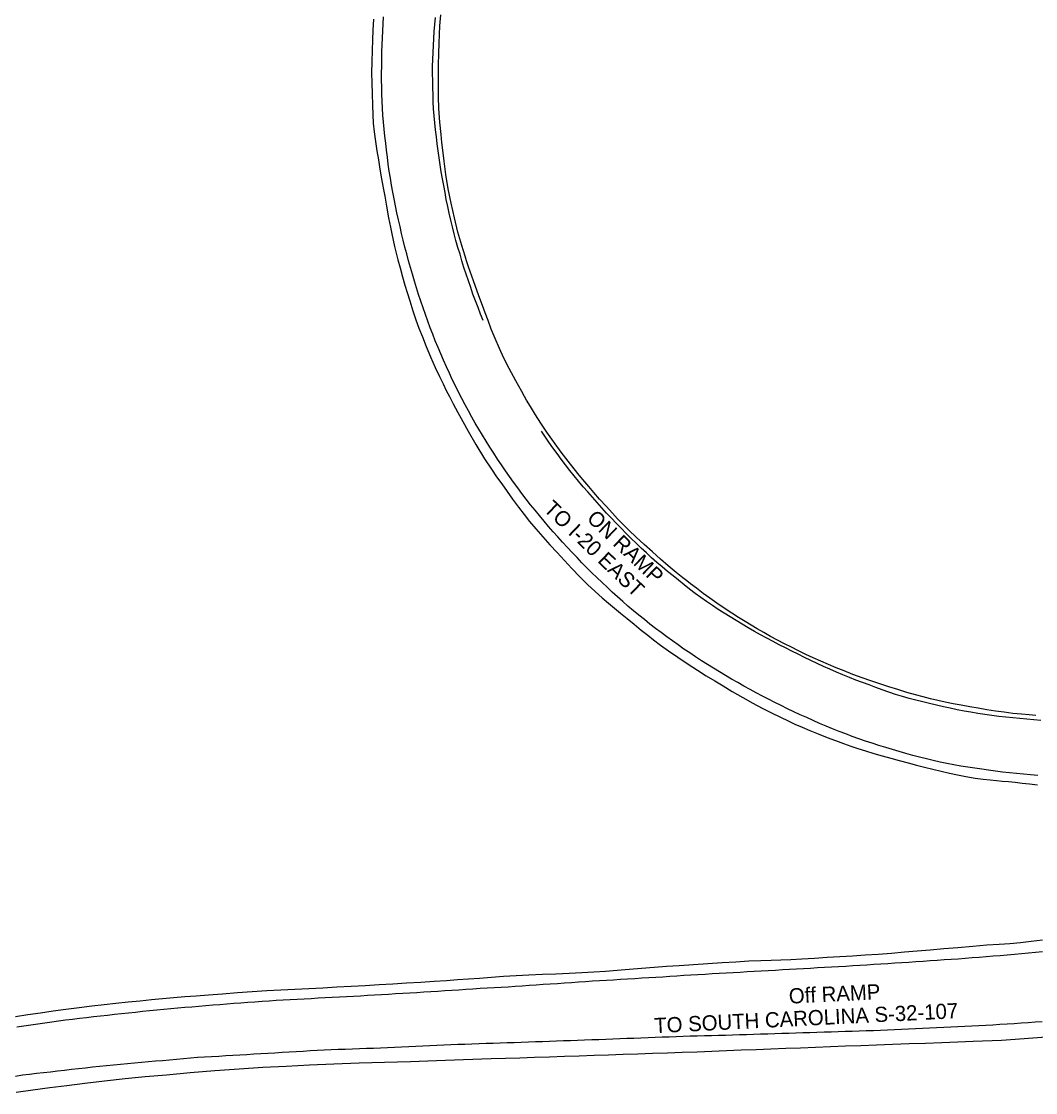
# Model space of a CAD drawing. Extents: x 1961683 to 1977751, y 798292 to 805767.
# Drawn here: x 1963000.6 to 1963360.5, y 799190.8 to 799570.9 of the extents above; entities that cross this region are included whole.
import ezdxf

# ---------------------------------------------------------------- set-up
doc = ezdxf.new("R2010")
doc.units = 0
for name, color, linetype in [('RD_EX_Road', 7, 'Continuous'), ('RD_EX_Road_Paint', 7, 'Continuous'), ('RD_TX_RoadID', 7, 'Continuous')]:
    doc.layers.add(name, color=color, linetype=linetype)

msp = doc.modelspace()

# ---------------------------------------------------------------- linework, layer by layer
at = {"layer": 'RD_EX_Road'}
for points in [[(1963125.57, 799571.68), (1963125.33, 799567.81), (1963125.16, 799564.4), (1963125.02, 799560.65), (1963124.91, 799556.54), (1963124.9, 799552.68), (1963124.97, 799549.1), (1963125.05, 799545.27), (1963125.15, 799541.23), (1963125.27, 799537.74), (1963125.45, 799534.81), (1963125.77, 799531.7), (1963126.23, 799528.35), (1963126.74, 799525.06), (1963127.28, 799521.83), (1963127.85, 799518.49), (1963128.44, 799515.05), (1963129, 799511.89), (1963129.54, 799508.92), (1963130.19, 799505.36), (1963130.92, 799501.27), (1963131.53, 799497.95), (1963132, 799495.5), (1963132.48, 799493.24), (1963132.99, 799491.02), (1963133.56, 799488.74), (1963134.19, 799486.34), (1963134.98, 799483.5), (1963135.89, 799480.28), (1963136.71, 799477.37), (1963137.47, 799474.77), (1963138.39, 799471.74), (1963139.5, 799468.25), (1963140.59, 799465.02), (1963141.67, 799462.08), (1963142.88, 799458.95), (1963144.26, 799455.56), (1963145.8, 799451.91), (1963147.46, 799448.13), (1963148.95, 799444.9), (1963150.23, 799442.28), (1963151.37, 799439.99), (1963152.46, 799437.87), (1963153.84, 799435.25), (1963155.52, 799432.09), (1963157.25, 799428.89), (1963159.09, 799425.53), (1963161.81, 799420.83), (1963164.97, 799415.67), (1963167.37, 799412.03), (1963169.22, 799409.36), (1963171.05, 799406.79), (1963172.94, 799404.15), (1963174.92, 799401.4), (1963176.99, 799398.57), (1963178.97, 799395.95), (1963180.9, 799393.51), (1963183.11, 799390.87), (1963185.6, 799387.99), (1963188.14, 799385.17), (1963190.67, 799382.43), (1963193.28, 799379.61), (1963195.97, 799376.72), (1963198.74, 799373.85), (1963201.54, 799371.06), (1963204.21, 799368.56), (1963206.7, 799366.38), (1963208.96, 799364.44), (1963211.04, 799362.69), (1963213.23, 799360.89), (1963215.57, 799358.98), (1963218.03, 799356.97), (1963220.56, 799354.91), (1963222.84, 799353.08), (1963224.9, 799351.45), (1963227.34, 799349.62), (1963230.24, 799347.54), (1963233.54, 799345.27), (1963237.16, 799342.88), (1963240.55, 799340.69), (1963243.64, 799338.74), (1963246.61, 799336.89), (1963249.56, 799335.09), (1963252.87, 799333.11), (1963256.55, 799330.98), (1963260.1, 799329.02), (1963263.48, 799327.25), (1963266.76, 799325.59), (1963269.93, 799324.03), (1963272.69, 799322.69), (1963275.09, 799321.56), (1963277.63, 799320.42), (1963280.41, 799319.26), (1963283.37, 799318.05), (1963286.49, 799316.83), (1963289.47, 799315.7), (1963292.27, 799314.68), (1963294.88, 799313.76), (1963297.36, 799312.91), (1963300.1, 799312.02), (1963303.1, 799311.11), (1963306.09, 799310.26), (1963309.06, 799309.47), (1963312.12, 799308.64), (1963315.25, 799307.77), (1963318.24, 799306.96), (1963321.07, 799306.22), (1963323.98, 799305.5), (1963326.97, 799304.79), (1963329.87, 799304.13), (1963332.71, 799303.52), (1963335.77, 799302.94), (1963339.01, 799302.42), (1963341.91, 799302.04), (1963344.38, 799301.78), (1963346.61, 799301.56), (1963348.66, 799301.35), (1963350.84, 799301.14), (1963353.19, 799300.9), (1963355.68, 799300.62), (1963358.31, 799300.31), (1963361.12, 799300.01)], [(1963360.54, 799324.62), (1963358.18, 799324.8), (1963355.44, 799325.03), (1963352.45, 799325.33), (1963349.34, 799325.73), (1963346.21, 799326.19), (1963343.16, 799326.67), (1963340.15, 799327.16), (1963337.11, 799327.68), (1963334.12, 799328.22), (1963331.21, 799328.76), (1963328.42, 799329.32), (1963325.77, 799329.91), (1963323.18, 799330.52), (1963320.59, 799331.17), (1963317.86, 799331.92), (1963314.84, 799332.81), (1963311.65, 799333.78), (1963308.44, 799334.78), (1963305.23, 799335.81), (1963302.07, 799336.86), (1963298.9, 799337.97), (1963295.68, 799339.18), (1963292.58, 799340.4), (1963289.74, 799341.56), (1963287.03, 799342.7), (1963284.31, 799343.86), (1963281.6, 799345.06), (1963278.93, 799346.3), (1963276.33, 799347.56), (1963273.86, 799348.82), (1963271.41, 799350.09), (1963268.9, 799351.38), (1963266.4, 799352.7), (1963264.01, 799354.06), (1963261.73, 799355.41), (1963259.56, 799356.69), (1963257.39, 799357.99), (1963255.11, 799359.41), (1963252.66, 799360.97), (1963250.01, 799362.71), (1963247.36, 799364.5), (1963244.91, 799366.22), (1963242.54, 799367.94), (1963240.13, 799369.74), (1963238.05, 799371.3), (1963236.71, 799372.34), (1963235.28, 799373.48), (1963232.95, 799375.37), (1963230.16, 799377.69), (1963227.36, 799380.1), (1963224.51, 799382.64), (1963221.57, 799385.31), (1963218.73, 799387.94), (1963216.18, 799390.37), (1963213.97, 799392.55), (1963212.14, 799394.42), (1963210.3, 799396.39), (1963208.06, 799398.84), (1963205.76, 799401.43), (1963203.72, 799403.77), (1963201.96, 799405.83), (1963200.49, 799407.57), (1963198.57, 799409.9), (1963195.5, 799413.76), (1963192.15, 799418.09), (1963189.39, 799421.82), (1963187.04, 799425.15), (1963184.92, 799428.31), (1963182.99, 799431.32), (1963181.23, 799434.22), (1963179.87, 799436.54), (1963179.14, 799437.83), (1963178.17, 799439.59), (1963176.09, 799443.32), (1963173.7, 799447.71), (1963171.81, 799451.44), (1963170.21, 799454.89), (1963168.69, 799458.39), (1963167.32, 799461.75), (1963166.18, 799464.75), (1963165.17, 799467.5), (1963164.19, 799470.1), (1963162.91, 799473.57), (1963160.99, 799478.91), (1963159.25, 799483.81), (1963158.53, 799485.92), (1963158.02, 799487.63), (1963156.89, 799491.35), (1963155.51, 799496.19), (1963154.24, 799501.24), (1963153.09, 799506.4), (1963152.09, 799511.57), (1963151.25, 799516.59), (1963150.59, 799521.33), (1963150.11, 799525.28), (1963149.82, 799527.95), (1963149.54, 799530.78), (1963149.14, 799535.21), (1963148.78, 799540.07), (1963148.63, 799544.17), (1963148.6, 799547.92), (1963148.6, 799551.71), (1963148.62, 799555.56), (1963148.7, 799559.52), (1963148.8, 799563.22), (1963148.93, 799566.29), (1963149.12, 799569.41), (1963149.43, 799573.25)], [(1963362.91, 799244.86), (1963358.9, 799244.42), (1963355.11, 799243.98), (1963351.37, 799243.61), (1963347.49, 799243.34), (1963343.18, 799243.06), (1963338.17, 799242.65), (1963332.92, 799242.19), (1963327.89, 799241.74), (1963323.07, 799241.32), (1963318.51, 799240.93), (1963314, 799240.56), (1963309.36, 799240.17), (1963304.67, 799239.8), (1963300.02, 799239.49), (1963295.46, 799239.21), (1963291.02, 799238.94), (1963286.57, 799238.68), (1963281.99, 799238.41), (1963277.57, 799238.14), (1963273.63, 799237.91), (1963270.03, 799237.74), (1963266.64, 799237.65), (1963263.02, 799237.56), (1963258.74, 799237.37), (1963254.06, 799237.11), (1963249.23, 799236.82), (1963244.23, 799236.5), (1963239.07, 799236.16), (1963234.04, 799235.82), (1963229.48, 799235.5), (1963225.11, 799235.16), (1963220.68, 799234.78), (1963216.29, 799234.41), (1963212.04, 799234.07), (1963207.88, 799233.78), (1963203.73, 799233.52), (1963199.46, 799233.27), (1963194.96, 799233.05), (1963190.27, 799232.84), (1963185.46, 799232.64), (1963180.7, 799232.44), (1963176.14, 799232.22), (1963171.72, 799231.95), (1963167.36, 799231.63), (1963163.16, 799231.3), (1963159.24, 799231.02), (1963155.39, 799230.74), (1963151.4, 799230.45), (1963147.1, 799230.15), (1963142.29, 799229.85), (1963137.31, 799229.56), (1963132.46, 799229.26), (1963127.61, 799228.98), (1963122.65, 799228.71), (1963117.63, 799228.44), (1963112.59, 799228.15), (1963107.56, 799227.86), (1963102.57, 799227.59), (1963097.62, 799227.33), (1963092.7, 799227.11), (1963087.72, 799226.86), (1963082.55, 799226.53), (1963077.28, 799226.14), (1963072.03, 799225.73), (1963067.06, 799225.34), (1963062.65, 799225.02), (1963058.57, 799224.72), (1963054.6, 799224.38), (1963050.7, 799224.03), (1963046.8, 799223.67), (1963042.78, 799223.28), (1963038.48, 799222.84), (1963034.13, 799222.38), (1963029.93, 799221.93), (1963025.65, 799221.45), (1963021.06, 799220.88), (1963016.39, 799220.25), (1963011.87, 799219.63), (1963007.41, 799219), (1963002.96, 799218.35), (1962998.51, 799217.68)], [(1963364.27, 799210.46), (1963356.46, 799209.83), (1963348.36, 799209.32), (1963338.38, 799208.87), (1963332.86, 799208.66), (1963327.22, 799208.45), (1963321.46, 799208.24), (1963315.57, 799208.04), (1963309.69, 799207.84), (1963303.97, 799207.63), (1963298.41, 799207.42), (1963293, 799207.2), (1963287.68, 799206.99), (1963282.38, 799206.78), (1963277.09, 799206.58), (1963271.81, 799206.38), (1963266.55, 799206.18), (1963261.3, 799205.98), (1963256.06, 799205.78), (1963250.82, 799205.58), (1963245.58, 799205.38), (1963240.34, 799205.18), (1963235.09, 799204.99), (1963229.83, 799204.81), (1963224.58, 799204.62), (1963219.36, 799204.44), (1963214.16, 799204.26), (1963208.98, 799204.08), (1963203.79, 799203.9), (1963198.57, 799203.73), (1963193.3, 799203.55), (1963188, 799203.38), (1963182.72, 799203.21), (1963177.52, 799203.04), (1963172.39, 799202.87), (1963167.34, 799202.71), (1963157.49, 799202.37), (1963147.94, 799202.01), (1963138.63, 799201.68), (1963129.45, 799201.42), (1963120.41, 799201.17), (1963111.53, 799200.86), (1963102.88, 799200.5), (1963094.51, 799200.09), (1963086.23, 799199.64), (1963077.86, 799199.11), (1963069.31, 799198.5), (1963060.52, 799197.76), (1963052.06, 799197), (1963044.54, 799196.31), (1963037.41, 799195.61), (1963030.14, 799194.81), (1963023.12, 799193.99), (1963016.76, 799193.23), (1963010.73, 799192.47), (1963004.69, 799191.64), (1962998.77, 799190.78)]]:
    msp.add_lwpolyline(points, dxfattribs=at)
at = {"layer": 'RD_EX_Road_Paint'}
for points in [[(1963361.21, 799303.35), (1963358.72, 799303.53), (1963356.23, 799303.75), (1963353.74, 799303.98), (1963351.25, 799304.23), (1963348.77, 799304.51), (1963346.3, 799304.83), (1963343.82, 799305.17), (1963341.35, 799305.53), (1963338.88, 799305.88), (1963336.4, 799306.24), (1963333.94, 799306.64), (1963331.48, 799307.08), (1963329.03, 799307.57), (1963326.59, 799308.08), (1963324.15, 799308.64), (1963321.72, 799309.22), (1963319.3, 799309.83), (1963316.88, 799310.45), (1963314.47, 799311.11), (1963312.07, 799311.81), (1963309.67, 799312.52), (1963307.28, 799313.24), (1963304.9, 799313.98), (1963302.51, 799314.73), (1963300.14, 799315.52), (1963297.78, 799316.34), (1963295.44, 799317.2), (1963293.1, 799318.07), (1963290.77, 799318.98), (1963288.45, 799319.91), (1963286.14, 799320.86), (1963283.83, 799321.82), (1963281.54, 799322.82), (1963279.26, 799323.84), (1963276.99, 799324.88), (1963274.72, 799325.93), (1963272.47, 799327), (1963270.22, 799328.1), (1963267.99, 799329.22), (1963265.76, 799330.36), (1963263.55, 799331.51), (1963261.34, 799332.68), (1963259.14, 799333.87), (1963256.95, 799335.07), (1963254.77, 799336.29), (1963252.59, 799337.52), (1963250.44, 799338.79), (1963248.3, 799340.08), (1963246.17, 799341.39), (1963244.04, 799342.7), (1963241.93, 799344.04), (1963239.84, 799345.41), (1963237.76, 799346.8), (1963235.7, 799348.2), (1963233.65, 799349.63), (1963231.6, 799351.07), (1963229.58, 799352.54), (1963227.57, 799354.02), (1963225.58, 799355.53), (1963223.61, 799357.07), (1963221.65, 799358.62), (1963219.7, 799360.18), (1963217.76, 799361.77), (1963215.84, 799363.37), (1963213.96, 799365.01), (1963212.12, 799366.7), (1963210.28, 799368.4), (1963208.46, 799370.11), (1963206.64, 799371.82), (1963204.82, 799373.53), (1963203.02, 799375.27), (1963201.25, 799377.04), (1963199.5, 799378.82), (1963197.77, 799380.62), (1963196.05, 799382.43), (1963194.33, 799384.25), (1963192.64, 799386.09), (1963190.97, 799387.96), (1963189.32, 799389.83), (1963187.67, 799391.71), (1963186.05, 799393.61), (1963184.44, 799395.53), (1963182.86, 799397.46), (1963181.29, 799399.41), (1963179.75, 799401.38), (1963178.23, 799403.36), (1963176.73, 799405.36), (1963175.26, 799407.38), (1963173.81, 799409.42), (1963172.38, 799411.47), (1963170.97, 799413.53), (1963169.57, 799415.6), (1963168.2, 799417.7), (1963166.86, 799419.81), (1963165.53, 799421.93), (1963164.21, 799424.05), (1963162.92, 799426.19), (1963161.66, 799428.35), (1963160.43, 799430.52), (1963159.23, 799432.71), (1963158.04, 799434.91), (1963156.87, 799437.12), (1963155.72, 799439.34), (1963154.6, 799441.58), (1963153.51, 799443.83), (1963152.46, 799446.1), (1963151.43, 799448.38), (1963150.42, 799450.66), (1963149.42, 799452.95), (1963148.44, 799455.25), (1963147.49, 799457.56), (1963146.57, 799459.89), (1963145.68, 799462.22), (1963144.8, 799464.56), (1963143.96, 799466.92), (1963143.15, 799469.28), (1963142.34, 799471.65), (1963141.55, 799474.02), (1963140.78, 799476.4), (1963140.06, 799478.79), (1963139.34, 799481.19), (1963138.62, 799483.58), (1963137.94, 799485.99), (1963137.32, 799488.41), (1963136.69, 799490.83), (1963136.06, 799493.25), (1963135.47, 799495.68), (1963134.96, 799498.12), (1963134.44, 799500.57), (1963133.88, 799503.01), (1963133.37, 799505.45), (1963132.91, 799507.91), (1963132.45, 799510.37), (1963131.98, 799512.82), (1963131.54, 799515.28), (1963131.16, 799517.75), (1963130.8, 799520.23), (1963130.5, 799522.71), (1963130.2, 799525.19), (1963129.88, 799527.67), (1963129.59, 799530.15), (1963129.34, 799532.64), (1963129.11, 799535.13), (1963128.91, 799537.62), (1963128.74, 799540.11), (1963128.62, 799542.61), (1963128.52, 799545.11), (1963128.47, 799547.61), (1963128.44, 799550.11), (1963128.44, 799552.6), (1963128.46, 799555.1), (1963128.5, 799557.6), (1963128.55, 799560.1), (1963128.62, 799562.6), (1963128.71, 799565.1), (1963128.82, 799567.6), (1963128.96, 799570.09), (1963129.12, 799572.59)], [(1963164.48, 799464.76), (1963163.56, 799467.09), (1963162.64, 799469.41), (1963161.75, 799471.75), (1963160.85, 799474.08), (1963160.08, 799476.46), (1963159.31, 799478.84), (1963158.48, 799481.19), (1963157.65, 799483.55), (1963156.95, 799485.95), (1963156.25, 799488.35), (1963155.52, 799490.74), (1963154.79, 799493.13), (1963154.19, 799495.56), (1963153.58, 799497.98), (1963153.01, 799500.42), (1963152.45, 799502.86), (1963151.91, 799505.3), (1963151.37, 799507.74), (1963150.94, 799510.2), (1963150.52, 799512.66), (1963150.06, 799515.12), (1963149.59, 799517.58), (1963149.21, 799520.05), (1963148.84, 799522.52), (1963148.49, 799524.99), (1963148.15, 799527.47), (1963147.87, 799529.95), (1963147.59, 799532.44), (1963147.33, 799534.93), (1963147.07, 799537.41), (1963146.89, 799539.9), (1963146.78, 799542.4), (1963146.7, 799544.9), (1963146.64, 799547.4), (1963146.58, 799549.9), (1963146.52, 799552.4), (1963146.47, 799554.89), (1963146.62, 799557.39), (1963146.76, 799559.89), (1963146.84, 799562.38), (1963146.9, 799564.88), (1963147.07, 799567.37), (1963147.3, 799569.86), (1963147.5, 799572.35)], [(1963362.33, 799322.86), (1963359.84, 799323.05), (1963357.35, 799323.25), (1963354.86, 799323.51), (1963352.38, 799323.77), (1963349.9, 799324.02), (1963347.41, 799324.29), (1963344.94, 799324.64), (1963342.47, 799325), (1963340, 799325.36), (1963337.53, 799325.74), (1963335.07, 799326.18), (1963332.62, 799326.65), (1963330.17, 799327.17), (1963327.74, 799327.71), (1963325.3, 799328.26), (1963322.86, 799328.81), (1963320.44, 799329.41), (1963318.02, 799330.03), (1963315.6, 799330.67), (1963313.19, 799331.32), (1963310.81, 799332.08), (1963308.45, 799332.89), (1963306.09, 799333.73), (1963303.75, 799334.58), (1963301.4, 799335.44), (1963299.05, 799336.29), (1963296.72, 799337.19), (1963294.4, 799338.11), (1963292.09, 799339.06), (1963289.78, 799340.03), (1963287.5, 799341.03), (1963285.21, 799342.04), (1963282.94, 799343.08), (1963280.67, 799344.13), (1963278.43, 799345.23), (1963276.19, 799346.34), (1963273.96, 799347.46), (1963271.72, 799348.57), (1963269.5, 799349.72), (1963267.3, 799350.9), (1963265.09, 799352.08), (1963262.88, 799353.24), (1963260.68, 799354.43), (1963258.53, 799355.69), (1963256.38, 799356.97), (1963254.25, 799358.27), (1963252.11, 799359.58), (1963250, 799360.91), (1963247.89, 799362.24), (1963245.82, 799363.65), (1963243.76, 799365.06), (1963241.72, 799366.5), (1963239.68, 799367.95), (1963237.71, 799369.48), (1963235.74, 799371.03), (1963233.79, 799372.59), (1963231.83, 799374.14), (1963229.89, 799375.72), (1963227.96, 799377.31), (1963226.08, 799378.96), (1963224.21, 799380.61), (1963222.36, 799382.3), (1963220.53, 799383.99), (1963218.72, 799385.72), (1963216.92, 799387.46), (1963215.17, 799389.24), (1963213.42, 799391.03), (1963211.69, 799392.82), (1963209.95, 799394.62), (1963208.23, 799396.43), (1963206.51, 799398.25), (1963204.89, 799400.15), (1963203.28, 799402.06), (1963201.61, 799403.93), (1963199.94, 799405.79), (1963198.34, 799407.71), (1963196.75, 799409.63), (1963195.21, 799411.6), (1963193.67, 799413.57), (1963192.17, 799415.57), (1963190.68, 799417.58), (1963189.23, 799419.62), (1963187.79, 799421.66), (1963186.37, 799423.71), (1963185.15, 799425.48)], [(1962998.99, 799214.1), (1963001.46, 799214.46), (1963003.94, 799214.82), (1963006.41, 799215.17), (1963008.89, 799215.52), (1963011.36, 799215.87), (1963013.84, 799216.23), (1963016.32, 799216.54), (1963018.8, 799216.83), (1963021.28, 799217.13), (1963023.76, 799217.44), (1963026.25, 799217.73), (1963028.73, 799218.02), (1963031.21, 799218.3), (1963033.7, 799218.58), (1963036.18, 799218.85), (1963038.67, 799219.1), (1963041.15, 799219.37), (1963043.64, 799219.64), (1963046.13, 799219.87), (1963048.62, 799220.1), (1963051.11, 799220.35), (1963053.59, 799220.6), (1963056.08, 799220.83), (1963058.57, 799221.05), (1963061.06, 799221.25), (1963063.56, 799221.44), (1963066.05, 799221.65), (1963068.54, 799221.87), (1963071.03, 799222.08), (1963073.52, 799222.29), (1963076.01, 799222.48), (1963078.5, 799222.66), (1963081, 799222.83), (1963083.49, 799223), (1963085.99, 799223.19), (1963088.48, 799223.38), (1963090.97, 799223.52), (1963093.47, 799223.65), (1963095.97, 799223.8), (1963098.46, 799223.96), (1963100.96, 799224.09), (1963103.45, 799224.22), (1963105.95, 799224.36), (1963108.45, 799224.5), (1963110.94, 799224.62), (1963113.44, 799224.73), (1963115.94, 799224.87), (1963118.43, 799225.01), (1963120.93, 799225.16), (1963123.42, 799225.3), (1963125.92, 799225.45), (1963128.41, 799225.6), (1963130.91, 799225.75), (1963133.41, 799225.9), (1963135.9, 799226.05), (1963138.4, 799226.19), (1963140.89, 799226.33), (1963143.39, 799226.48), (1963145.88, 799226.64), (1963148.38, 799226.81), (1963150.87, 799226.95), (1963153.37, 799227.09), (1963155.86, 799227.26), (1963158.36, 799227.44), (1963160.85, 799227.61), (1963163.34, 799227.79), (1963165.84, 799227.92), (1963168.34, 799228.05), (1963170.83, 799228.2), (1963173.33, 799228.35), (1963175.82, 799228.52), (1963178.32, 799228.68), (1963180.81, 799228.85), (1963183.3, 799229.03), (1963185.8, 799229.2), (1963188.29, 799229.37), (1963190.79, 799229.53), (1963193.28, 799229.69), (1963195.77, 799229.87), (1963198.27, 799230.06), (1963200.76, 799230.22), (1963203.26, 799230.38), (1963205.75, 799230.54), (1963208.24, 799230.71), (1963210.74, 799230.85), (1963213.24, 799230.98), (1963215.73, 799231.15), (1963218.22, 799231.32), (1963220.72, 799231.49), (1963223.21, 799231.65), (1963225.71, 799231.78), (1963228.21, 799231.9), (1963230.7, 799232.06), (1963233.2, 799232.23), (1963235.69, 799232.39), (1963238.18, 799232.55), (1963240.68, 799232.69), (1963243.18, 799232.83), (1963245.67, 799232.99), (1963248.16, 799233.15), (1963250.66, 799233.28), (1963253.16, 799233.41), (1963255.65, 799233.55), (1963258.15, 799233.7), (1963260.64, 799233.85), (1963263.14, 799234.01), (1963265.64, 799234.14), (1963268.13, 799234.26), (1963270.63, 799234.42), (1963273.12, 799234.59), (1963275.62, 799234.7), (1963278.12, 799234.8), (1963280.61, 799234.96), (1963283.1, 799235.12), (1963285.6, 799235.26), (1963288.1, 799235.39), (1963290.59, 799235.53), (1963293.09, 799235.67), (1963295.58, 799235.84), (1963298.08, 799236.01), (1963300.57, 799236.17), (1963303.07, 799236.32), (1963305.56, 799236.47), (1963308.06, 799236.63), (1963310.55, 799236.77), (1963313.05, 799236.91), (1963315.54, 799237.09), (1963318.03, 799237.28), (1963320.53, 799237.45), (1963323.02, 799237.61), (1963325.52, 799237.78), (1963328.01, 799237.96), (1963330.5, 799238.13), (1963333, 799238.29), (1963335.49, 799238.47), (1963337.98, 799238.66), (1963340.47, 799238.87), (1963342.96, 799239.09), (1963345.45, 799239.29), (1963347.95, 799239.48), (1963350.44, 799239.69), (1963352.93, 799239.9), (1963355.42, 799240.14), (1963357.9, 799240.41), (1963360.39, 799240.65), (1963362.88, 799240.88)], [(1962998.51, 799196.61), (1963000.97, 799197.04), (1963003.45, 799197.35), (1963005.94, 799197.64), (1963008.42, 799197.92), (1963010.9, 799198.2), (1963013.39, 799198.48), (1963015.87, 799198.76), (1963018.36, 799199.04), (1963020.84, 799199.32), (1963023.32, 799199.6), (1963025.81, 799199.88), (1963028.29, 799200.16), (1963030.78, 799200.42), (1963033.27, 799200.64), (1963035.76, 799200.87), (1963038.25, 799201.09), (1963040.73, 799201.32), (1963043.22, 799201.55), (1963045.71, 799201.77), (1963048.2, 799202), (1963050.69, 799202.22), (1963053.18, 799202.45), (1963055.67, 799202.68), (1963058.16, 799202.9), (1963060.65, 799203.13), (1963063.14, 799203.3), (1963065.64, 799203.45), (1963068.13, 799203.6), (1963070.63, 799203.74), (1963073.12, 799203.89), (1963075.62, 799204.04), (1963078.11, 799204.19), (1963080.61, 799204.34), (1963083.11, 799204.48), (1963085.6, 799204.63), (1963088.1, 799204.78), (1963090.59, 799204.93), (1963093.09, 799205.07), (1963095.58, 799205.22), (1963098.08, 799205.37), (1963100.57, 799205.52), (1963103.07, 799205.67), (1963105.56, 799205.81), (1963108.06, 799205.96), (1963110.56, 799206.05), (1963113.05, 799206.14), (1963115.55, 799206.23), (1963118.05, 799206.32), (1963120.55, 799206.41), (1963123.04, 799206.5), (1963125.54, 799206.6), (1963128.04, 799206.71), (1963130.54, 799206.82), (1963133.03, 799206.93), (1963135.53, 799207.04), (1963138.03, 799207.15), (1963140.52, 799207.26), (1963143.02, 799207.36), (1963145.52, 799207.47), (1963148.02, 799207.58), (1963150.51, 799207.69), (1963153.01, 799207.8), (1963155.51, 799207.91), (1963158.01, 799207.99), (1963160.5, 799208.08), (1963163, 799208.17), (1963165.5, 799208.26), (1963168, 799208.34), (1963170.5, 799208.43), (1963172.99, 799208.52), (1963175.49, 799208.6), (1963177.99, 799208.69), (1963180.49, 799208.78), (1963182.99, 799208.87), (1963185.48, 799208.95), (1963187.98, 799209.04), (1963190.48, 799209.13), (1963192.98, 799209.22), (1963195.48, 799209.3), (1963197.97, 799209.39), (1963200.47, 799209.49), (1963202.97, 799209.58), (1963205.47, 799209.67), (1963207.96, 799209.76), (1963210.46, 799209.86), (1963212.96, 799209.95), (1963215.46, 799210.04), (1963217.96, 799210.13), (1963220.45, 799210.23), (1963222.95, 799210.32), (1963225.45, 799210.41), (1963227.95, 799210.51), (1963230.44, 799210.6), (1963232.94, 799210.69), (1963235.44, 799210.78), (1963237.94, 799210.86), (1963240.44, 799210.93), (1963242.94, 799211), (1963245.43, 799211.07), (1963247.93, 799211.14), (1963250.43, 799211.21), (1963252.93, 799211.29), (1963255.43, 799211.36), (1963257.93, 799211.44), (1963260.43, 799211.52), (1963262.92, 799211.6), (1963265.42, 799211.68), (1963267.92, 799211.76), (1963270.42, 799211.84), (1963272.92, 799211.92), (1963275.42, 799212), (1963277.91, 799212.08), (1963280.41, 799212.16), (1963282.91, 799212.23), (1963285.41, 799212.31), (1963287.91, 799212.39), (1963290.41, 799212.47), (1963292.9, 799212.54), (1963295.4, 799212.62), (1963297.9, 799212.7), (1963300.4, 799212.78), (1963302.9, 799212.86), (1963305.39, 799212.97), (1963307.89, 799213.08), (1963310.39, 799213.19), (1963312.89, 799213.31), (1963315.38, 799213.42), (1963317.88, 799213.53), (1963320.38, 799213.64), (1963322.87, 799213.75), (1963325.37, 799213.86), (1963327.87, 799213.97), (1963330.37, 799214.08), (1963332.86, 799214.21), (1963335.36, 799214.34), (1963337.85, 799214.47), (1963340.35, 799214.6), (1963342.85, 799214.73), (1963345.34, 799214.86), (1963347.84, 799215.02), (1963350.33, 799215.19), (1963352.82, 799215.35), (1963355.32, 799215.52), (1963357.81, 799215.69), (1963360.31, 799215.85), (1963362.8, 799216.02)]]:
    msp.add_lwpolyline(points, dxfattribs=at)

# ---------------------------------------------------------------- texts
at = {"layer": 'RD_TX_RoadID'}
for s, rotation, p in [('TO I-20 EAST', 316.3641, (1963185.61, 799397.52)), ('ON RAMP', 316.3641, (1963200.89, 799394.14)), ('Off RAMP', 2.846, (1963273.05, 799222.32)), ('TO SOUTH CAROLINA S-32-107', 2.846, (1963225.3, 799211.84))]:
    msp.add_text(s, height=5.4, rotation=rotation, dxfattribs=at).set_placement(p)

doc.saveas('drawing.dxf')
